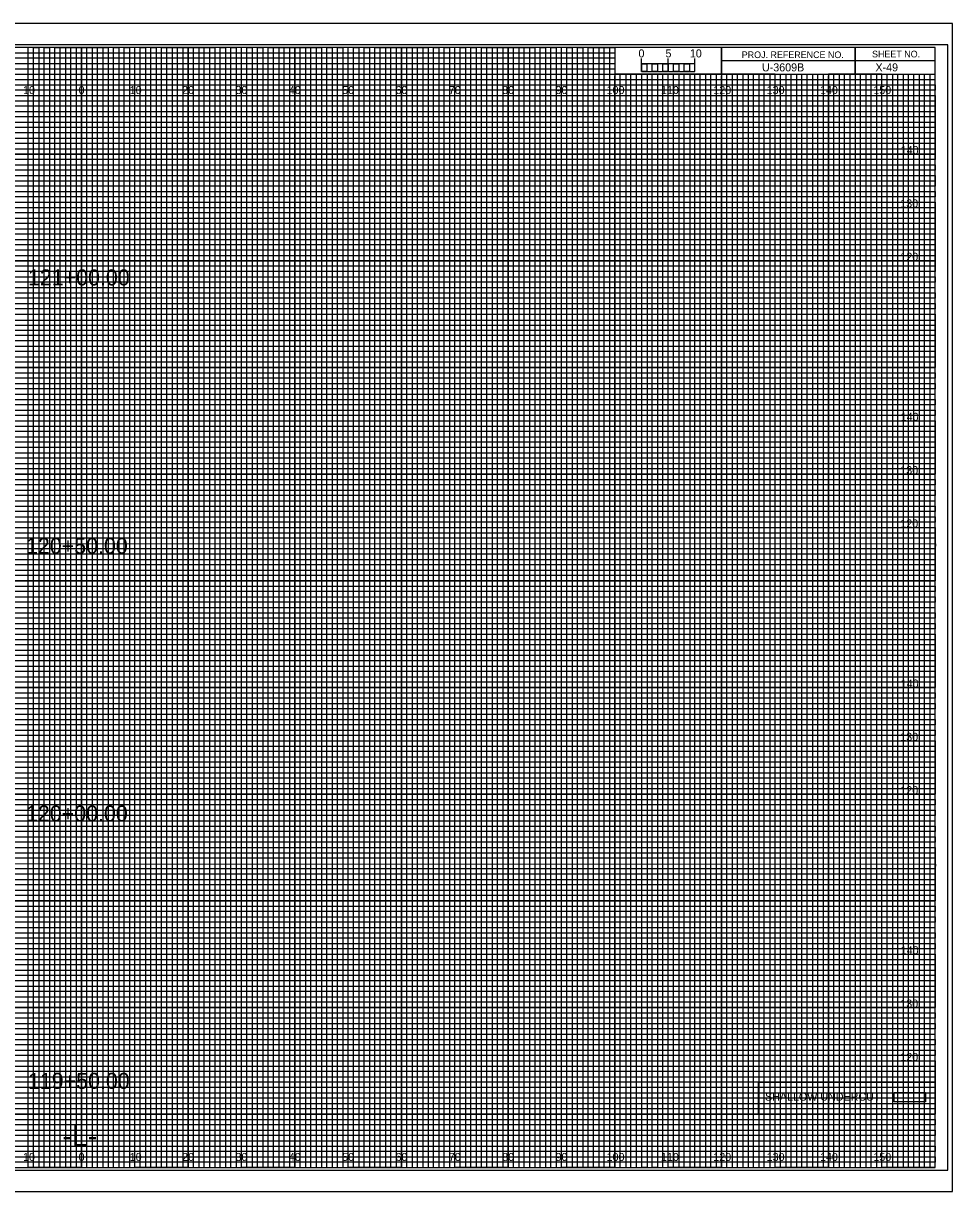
# Model space of a CAD drawing. Extents: x -13 to 329, y -17 to 10994.
# Drawn here: x 149.1 to 323.3, y 10335.5 to 10554.5 of the extents above; entities that cross this region are included whole.
import ezdxf

# ---------------------------------------------------------------- set-up
doc = ezdxf.new("R2010")
doc.units = 0
for name, color, linetype in [('Prop DSN Text', 7, 'Continuous'), ('Prop Grid Mask', 7, 'Continuous'), ('Prop Road Plan_ Recs - UC Shallow (pattern)', 7, 'Continuous'), ('Prop XS Alignment Label', 7, 'Continuous'), ('Prop XS Bar Scale Labels', 7, 'Continuous'), ('Prop XS Elevation Labels', 7, 'Continuous'), ('Prop XS Offset Labels', 7, 'Continuous'), ('Prop XS Project Number', 7, 'Continuous'), ('Prop XS Sheet Number', 7, 'Continuous'), ('Prop XS Station Labels', 7, 'Continuous'), ('Sheet Cross Section CELL', 7, 'Continuous'), ('Sheet Cross Section Grid Major CELL', 7, 'Continuous'), ('Sheet Cross Section Grid Middle CELL', 7, 'Continuous'), ('Sheet Cross Section Grid Minor 1 CELL', 7, 'Continuous'), ('Sheet Cross Section Grid Minor 2 CELL', 7, 'Continuous'), ('Sheet Cross Section Scale CELL', 7, 'Continuous'), ('Sheet Cutting Line CELL', 7, 'Continuous'), ('Sheet DOT Grid CELL', 7, 'Continuous'), ('Sheet Plot Border Inside CELL', 7, 'Continuous'), ('Sheet Plot Border Outside CELL', 7, 'Continuous')]:
    doc.layers.add(name, color=color, linetype=linetype)

msp = doc.modelspace()

# ---------------------------------------------------------------- linework, layer by layer
at = {"layer": 'Prop Grid Mask'}
msp.add_lwpolyline([(286.89, 10356.03), (320, 10356.03), (320, 10350), (286.89, 10350)], close=True, dxfattribs=at)
at = {"layer": 'Prop Road Plan_ Recs - UC Shallow (pattern)'}
msp.add_lwpolyline([(312.34, 10354.08), (318.23, 10354.08), (318.23, 10352.36), (312.34, 10352.36)], close=True, dxfattribs=at)
at = {"layer": 'Sheet Cross Section CELL'}
for p, q in [((305, 10550), (305, 10545)), ((305, 10545), (305, 10550)), ((280, 10547.5), (280, 10545)), ((320, 10547.49), (280, 10547.49)), ((280, 10545), (320, 10545))]:
    msp.add_line(p, q, dxfattribs=at)
for points in [[(320, 10550), (0, 10550), (0, 10340), (320, 10340)], [(280, 10550), (260, 10550), (260, 10545.03), (280, 10545.03)], [(320, 10550), (280, 10550), (280, 10545), (320, 10545)]]:
    msp.add_lwpolyline(points, close=True, dxfattribs=at)
at = {"layer": 'Sheet Cross Section Grid Major CELL'}
for p, q in [((150, 10550), (140, 10550)), ((150, 10340), (150, 10550)), ((170, 10550), (160, 10550)), ((160, 10550), (160, 10340)), ((170, 10340), (170, 10550)), ((190, 10550), (180, 10550)), ((180, 10550), (180, 10340)), ((190, 10340), (190, 10550)), ((210, 10550), (200, 10550)), ((200, 10550), (200, 10340)), ((210, 10340), (210, 10550)), ((230, 10550), (220, 10550)), ((220, 10550), (220, 10340)), ((230, 10340), (230, 10550)), ((250, 10550), (240, 10550)), ((240, 10550), (240, 10340)), ((250, 10340), (250, 10550)), ((260, 10550), (260, 10340)), ((270, 10340), (270, 10545)), ((290, 10545), (280, 10545)), ((280, 10545), (280, 10340)), ((290, 10340), (290, 10545)), ((310, 10545), (300, 10545)), ((300, 10545), (300, 10340)), ((310, 10340), (310, 10545)), ((160, 10340), (150, 10340)), ((180, 10340), (170, 10340)), ((200, 10340), (190, 10340)), ((220, 10340), (210, 10340)), ((240, 10340), (230, 10340)), ((260, 10340), (250, 10340)), ((280, 10340), (270, 10340)), ((300, 10340), (290, 10340)), ((320, 10340), (310, 10340)), ((320, 10340), (320, 10340))]:
    msp.add_line(p, q, dxfattribs=at)
for points in [[(0, 10540), (320, 10540), (320, 10530), (0, 10530)], [(0, 10520), (320, 10520), (320, 10510), (0, 10510)], [(0, 10500), (320, 10500), (320, 10490), (0, 10490)], [(0, 10480), (320, 10480), (320, 10470), (0, 10470)], [(0, 10460), (320, 10460), (320, 10450), (0, 10450)], [(0, 10440), (320, 10440), (320, 10430), (0, 10430)], [(0, 10420), (320, 10420), (320, 10410), (0, 10410)], [(0, 10400), (320, 10400), (320, 10390), (0, 10390)], [(0, 10380), (320, 10380), (320, 10370), (0, 10370)], [(0, 10360), (320, 10360), (320, 10350), (0, 10350)]]:
    msp.add_lwpolyline(points, dxfattribs=at)
at = {"layer": 'Sheet Cross Section Grid Middle CELL'}
for points in [[(145, 10340), (155, 10340), (155, 10550), (165, 10550), (165, 10340), (175, 10340), (175, 10550), (185, 10550), (185, 10340), (195, 10340), (195, 10550), (205, 10550), (205, 10340), (215, 10340), (215, 10550), (225, 10550), (225, 10340), (235, 10340), (235, 10550), (245, 10550), (245, 10340), (255, 10340), (255, 10550), (259.93, 10550), (260, 10550), (260, 10545), (264.99, 10545), (264.99, 10340), (275, 10340), (275, 10545), (285, 10545), (285, 10340), (295, 10340), (295, 10545), (305, 10545), (305, 10340), (315, 10340), (315, 10545)], [(0, 10545), (275, 10545)], [(0, 10525), (320, 10525), (320, 10535), (0, 10535)], [(0, 10505), (320, 10505), (320, 10515), (0, 10515)], [(0, 10485), (320, 10485), (320, 10495), (0, 10495)], [(0, 10465), (320, 10465), (320, 10475), (0, 10475)], [(0, 10445), (320, 10445), (320, 10455), (0, 10455)], [(0, 10425), (320, 10425), (320, 10435), (0, 10435)], [(0, 10405), (320, 10405), (320, 10415), (0, 10415)], [(0, 10385), (320, 10385), (320, 10395), (0, 10395)], [(0, 10365), (320, 10365), (320, 10375), (0, 10375)], [(0, 10345), (320, 10345), (320, 10355), (0, 10355)]]:
    msp.add_lwpolyline(points, dxfattribs=at)
at = {"layer": 'Sheet Cross Section Grid Minor 1 CELL'}
for p, q in [((0, 10549), (260, 10549)), ((260, 10547.98), (0, 10547.98)), ((260, 10549), (260, 10547.98)), ((0, 10547), (260, 10547)), ((260, 10545.89), (0, 10545.89)), ((260, 10547), (260, 10545.89)), ((0, 10544), (320, 10544))]:
    msp.add_line(p, q, dxfattribs=at)
for points in [[(0, 10543), (270, 10543), (320, 10543), (320, 10542), (0, 10542)], [(0, 10541), (320, 10541), (320, 10539), (0, 10539)], [(0, 10538), (320, 10538), (320, 10537), (0, 10536.98)], [(0, 10536), (320, 10536), (320, 10534), (0, 10534)], [(0, 10533), (320, 10533), (320, 10532), (0, 10532)], [(0, 10531), (320, 10531), (320, 10529), (0, 10529)], [(0, 10528), (320, 10528), (320, 10527), (0, 10527)], [(0, 10526), (320, 10526), (320, 10524), (0, 10524)], [(0, 10523), (320, 10523), (320, 10522), (0, 10522)], [(0, 10521), (320, 10521), (320, 10519), (0, 10519)], [(0, 10518), (320, 10518), (320, 10517), (0, 10517)], [(0, 10516), (320, 10516), (320, 10513.95), (320, 10513), (320, 10512), (0, 10512)], [(0, 10514), (320, 10514), (320, 10513), (0, 10513)], [(0, 10511), (320, 10511), (320, 10509), (0, 10509.03)], [(0, 10509.03), (320, 10509), (320, 10508), (0, 10508)], [(0, 10507), (320, 10507), (320, 10506), (0, 10506)], [(0, 10504), (320, 10504), (320, 10503), (0, 10503)], [(0, 10502), (320, 10502), (320, 10501), (0, 10501)], [(-0.07, 10498.89), (320, 10498.89), (320, 10497.88), (-0.07, 10497.88)], [(0, 10497), (320, 10497), (320, 10496), (0, 10496)], [(0, 10494), (320, 10494), (320, 10493), (0, 10493)], [(0, 10492), (320, 10492), (320, 10491), (0, 10491)], [(0, 10489), (320, 10489), (320, 10488), (0, 10488)], [(0, 10487), (320, 10487), (320, 10486), (0, 10486)], [(0, 10484), (320, 10484), (320, 10483), (0, 10483)], [(0, 10482), (320, 10482), (320, 10481), (0, 10481)], [(0, 10479), (320, 10479), (319.99, 10477.98), (0, 10478)], [(0, 10477), (320, 10477), (320, 10476), (0, 10476)], [(0, 10474), (320, 10474), (320, 10473), (0, 10473)], [(0, 10472), (320, 10472), (320, 10471), (0, 10471)], [(0, 10469), (320, 10469), (320, 10468), (0, 10468)], [(0, 10467), (320, 10467), (320, 10466), (0, 10466)], [(0, 10464), (320, 10464), (320, 10463), (0, 10463)], [(0, 10462), (320, 10462), (320, 10461), (0, 10461)], [(0, 10459), (320, 10459), (320, 10458), (0, 10458)], [(0, 10456.99), (320.07, 10456.91), (320, 10456), (0, 10456)], [(0, 10454), (320, 10454), (320, 10453), (0, 10453)], [(0, 10452), (320, 10452), (320, 10451), (0, 10451)], [(0, 10449), (320, 10449), (320, 10448), (0, 10448)], [(0, 10447), (320, 10447), (320, 10446), (0, 10446)], [(0, 10444), (320, 10444), (320, 10443), (0, 10443)], [(0, 10442), (320, 10442), (320, 10441), (0, 10441)], [(0, 10439), (320, 10439), (320, 10438), (0, 10438)], [(0, 10437), (320, 10437), (320, 10436), (0, 10436)], [(0, 10434), (320, 10434), (320, 10433), (0, 10433)], [(0, 10432), (320, 10432), (320, 10431), (0, 10431)], [(0, 10429), (320, 10429), (320, 10428), (0, 10428)], [(0, 10427), (320, 10427), (320, 10426), (0, 10426)], [(0, 10424), (320, 10424), (320, 10423), (0, 10423)], [(0, 10422), (320, 10422), (320, 10421), (0, 10421)], [(0, 10419), (320, 10419), (319.99, 10417.98), (0, 10418)], [(0, 10417), (320, 10417), (320, 10416), (0, 10416)], [(0, 10414), (320, 10414), (320, 10413), (0, 10413)], [(0, 10412), (320, 10412), (320, 10411), (0, 10411)], [(0, 10409), (320, 10409), (320, 10408), (0, 10408)], [(0, 10407), (320, 10407), (320, 10406), (0, 10406)], [(0, 10404), (320, 10404), (320, 10403), (0, 10403)], [(0, 10402), (320, 10402), (320, 10401), (0, 10401)], [(0, 10399), (320, 10399), (320, 10398), (0, 10398)], [(0, 10396.99), (320.07, 10396.91), (320, 10396), (0, 10396)], [(0, 10394), (320, 10394), (320, 10393), (0, 10393)], [(0, 10392), (320, 10392), (320, 10391), (0, 10391)], [(0, 10389), (320, 10389), (320, 10388), (0, 10388)], [(0, 10387), (320, 10387), (320, 10386), (0, 10386)], [(0, 10384), (320, 10384), (320, 10383), (0, 10383)], [(0, 10382), (320, 10382), (320, 10381), (0, 10381)], [(0, 10379), (320, 10379), (320, 10378), (0, 10378)], [(0, 10377), (320, 10377), (320, 10376), (0, 10376)], [(0, 10374), (320, 10374), (320, 10373), (0, 10373)], [(0, 10372), (320, 10372), (320, 10371), (0, 10371)], [(0, 10369), (320, 10369), (320, 10368), (0, 10368)], [(0, 10367), (320, 10367), (320, 10366), (0, 10366)], [(0, 10364), (320, 10364), (320, 10363), (0, 10363)], [(0, 10362), (320, 10362), (320, 10361), (0, 10361)], [(0, 10359), (320, 10359), (320, 10358), (0, 10358)], [(0, 10357), (320, 10357), (320, 10356), (0, 10356)], [(0, 10354), (320, 10354), (320, 10353), (0, 10353)], [(0, 10352), (320, 10352), (320, 10351), (0, 10351)], [(0, 10349), (320, 10349), (320, 10348), (0, 10348)], [(0, 10347), (320, 10347), (320, 10346), (0, 10346)], [(0, 10344), (320, 10344), (320, 10343), (0, 10343)], [(0, 10342), (320, 10342), (320, 10341), (0, 10341)]]:
    msp.add_lwpolyline(points, dxfattribs=at)
at = {"layer": 'Sheet Cross Section Grid Minor 2 CELL'}
for p, q in [((267, 10545), (266.01, 10545)), ((266.01, 10545), (266.01, 10340)), ((267, 10340), (267, 10545)), ((269, 10545), (268, 10545)), ((268, 10545), (268, 10340)), ((269, 10340), (269, 10545)), ((266.01, 10340), (265, 10340)), ((268, 10340), (267, 10340))]:
    msp.add_line(p, q, dxfattribs=at)
for points in [[(150, 10340), (151, 10340), (151, 10550), (152, 10550), (152, 10340)], [(152, 10340), (153, 10340), (153, 10550), (154, 10550), (154, 10340)], [(155, 10340), (156, 10340), (156, 10550), (157, 10550), (157, 10340)], [(157, 10340), (158, 10340), (158, 10550), (159, 10550), (159, 10340)], [(160, 10340), (161, 10340), (161, 10550), (162, 10550), (162, 10340)], [(162, 10340), (163, 10340), (163, 10550), (164, 10550), (164, 10340)], [(165, 10340), (166, 10340), (166, 10550), (167, 10550), (167, 10340)], [(167, 10340), (168, 10340), (168, 10550), (169, 10550), (169, 10340)], [(170, 10340), (171, 10340), (171, 10550), (172, 10550), (172, 10340)], [(172, 10340), (173, 10340), (173, 10550), (174, 10550), (174, 10340)], [(175, 10340), (176, 10340), (176, 10550), (177, 10550), (177, 10340)], [(177, 10340), (178, 10340), (178, 10550), (179, 10550), (179, 10340)], [(180, 10340), (181, 10340), (181, 10550), (182, 10550), (182, 10340)], [(182, 10340), (183, 10340), (183, 10550), (184, 10550), (184, 10340)], [(185, 10340), (186, 10340), (186, 10550), (187, 10550), (187, 10340)], [(187, 10340), (188, 10340), (188, 10550), (189, 10550), (189, 10340)], [(190, 10340), (191, 10340), (191, 10550), (192, 10550), (192, 10340)], [(192, 10340), (193, 10340), (193, 10550), (194, 10550), (194, 10340)], [(195, 10340), (196, 10340), (196, 10550), (197, 10550), (197, 10340)], [(197, 10340), (198, 10340), (198, 10550), (199, 10550), (199, 10340)], [(200, 10340), (201, 10340), (201, 10550), (202, 10550), (202, 10340)], [(202, 10340), (203, 10340), (203, 10550), (204, 10550), (204, 10340)], [(205, 10340), (206, 10340), (206, 10550), (207, 10550), (207, 10340)], [(207, 10340), (208, 10340), (208, 10550), (209, 10550), (209, 10340)], [(210, 10340), (211, 10340), (211, 10550), (212, 10550), (212, 10340)], [(212, 10340), (213, 10340), (213, 10550), (214, 10550), (214, 10340)], [(215, 10340), (216, 10340), (216, 10550), (217, 10550), (217, 10340)], [(217, 10340), (218, 10340), (218, 10550), (219, 10550), (219, 10340)], [(220, 10340), (221, 10340), (221, 10550), (222, 10550), (222, 10340)], [(222, 10340), (223, 10340), (223, 10550), (224, 10550), (224, 10340)], [(225, 10340), (226, 10340), (226, 10550), (227, 10550), (227, 10340)], [(227, 10340), (228, 10340), (228, 10550), (229, 10550), (229, 10340)], [(230, 10340), (231, 10340), (231, 10550), (232, 10550), (232, 10340)], [(232, 10340), (233, 10340), (233, 10550), (234, 10550), (234, 10340)], [(235, 10340), (236, 10340), (236, 10550), (237, 10550), (237, 10340)], [(237, 10340), (238, 10340), (238, 10550), (239, 10550), (239, 10340)], [(240, 10340), (241, 10340), (241, 10550), (242, 10550), (242, 10340)], [(242, 10340), (243, 10340), (243, 10550), (244, 10550), (244, 10340)], [(245, 10340), (246, 10340), (246, 10550), (247, 10550), (247, 10340)], [(247, 10340), (248, 10340), (248, 10550), (249, 10550), (249, 10340)], [(250, 10340), (251, 10340), (251, 10550), (252, 10550), (252, 10340)], [(252, 10340), (253, 10340), (253, 10550), (254, 10550), (254, 10340)], [(255, 10340), (256, 10340), (256, 10550), (257, 10550), (257, 10340)], [(257, 10340), (258, 10340), (258, 10550), (259, 10550), (259, 10340)], [(260, 10340), (261, 10340), (261, 10545), (262.02, 10545), (262.02, 10340)], [(262, 10340), (263, 10340), (263, 10545), (263.99, 10545), (263.99, 10340)], [(270, 10340), (270.98, 10340), (270.98, 10545), (272, 10545), (272, 10340)], [(272, 10340), (273, 10340), (273, 10545), (274.05, 10545), (274.05, 10340)], [(275, 10340), (276, 10340), (276, 10545), (277, 10545), (277, 10340)], [(277, 10340), (278, 10340), (278, 10545), (279, 10545), (279, 10340)], [(280, 10340), (281, 10340), (281, 10545), (282, 10545), (282, 10340)], [(282, 10340), (283, 10340), (283, 10545), (284, 10545), (284, 10340)], [(285, 10340), (286, 10340), (286, 10545), (287, 10545), (287, 10340)], [(287, 10340), (288, 10340), (288, 10545), (289, 10545), (289, 10340)], [(290, 10340), (291, 10340), (291, 10545), (292, 10545), (292, 10340)], [(292, 10340), (293, 10340), (293, 10545), (294, 10545), (294, 10340)], [(295, 10340), (296, 10340), (296, 10545), (297, 10545), (297, 10340)], [(297, 10340), (298, 10340), (298, 10545), (299, 10545), (299, 10340)], [(300, 10340), (301, 10340), (301, 10545), (302, 10545), (302, 10340)], [(302, 10340), (303, 10340), (303, 10545), (304, 10545), (304, 10340)], [(305, 10340), (306, 10340), (306, 10545), (307, 10545), (307, 10340)], [(307, 10340), (308, 10340), (308, 10545), (309, 10545), (309, 10340)], [(310, 10340), (311, 10340), (311, 10545), (312, 10545), (312, 10340)], [(312, 10340), (313, 10340), (313, 10545), (314, 10545), (314, 10340)], [(315, 10340), (316, 10340), (316, 10545), (317, 10545), (317, 10340)], [(317, 10340), (318, 10340), (318, 10545), (319, 10545), (319, 10340)]]:
    msp.add_lwpolyline(points, dxfattribs=at)
at = {"layer": 'Sheet Cross Section Scale CELL'}
for p, q in [((265, 10545.49), (265, 10547.9)), ((265, 10546.9), (265, 10547.9)), ((270, 10545.49), (270, 10547.9)), ((275, 10545.49), (275, 10547.9)), ((275, 10546.9), (275, 10547.9))]:
    msp.add_line(p, q, dxfattribs=at)
for points in [[(275, 10546.9), (265, 10546.9), (265, 10545.49), (275, 10545.49)], [(265, 10546.9), (266, 10546.9), (266, 10545.49), (265, 10545.49)], [(267, 10546.9), (268, 10546.9), (268, 10545.49), (267, 10545.49)], [(269, 10546.9), (270, 10546.9), (270, 10545.49), (269, 10545.49)], [(271, 10546.9), (272, 10546.9), (272, 10545.49), (271, 10545.49)], [(273, 10546.9), (274, 10546.9), (274, 10545.49), (273, 10545.49)]]:
    msp.add_lwpolyline(points, close=True, dxfattribs=at)
at = {"layer": 'Sheet Cutting Line CELL'}
for p, q in [((323.3, 10554.5), (-13.4, 10554.5)), ((-13.4, 10335.5), (323.3, 10335.5))]:
    msp.add_line(p, q, dxfattribs=at)
at = {"layer": 'Sheet DOT Grid CELL'}
for p, q in [((150, 10340), (150, 10550)), ((160, 10340), (160, 10550)), ((170, 10340), (170, 10550)), ((180, 10340), (180, 10550)), ((190, 10340), (190, 10550)), ((200, 10340), (200, 10550)), ((210, 10340), (210, 10550)), ((220, 10340), (220, 10550)), ((230, 10340), (230, 10550)), ((240, 10340), (240, 10550)), ((250, 10340), (250, 10550)), ((260, 10340), (260, 10544.69)), ((270, 10340), (270, 10544.69)), ((280, 10340), (280, 10544.69)), ((290, 10340), (290, 10544.69)), ((300, 10340), (300, 10544.69)), ((310, 10340), (310, 10544.69)), ((0, 10540), (320, 10540)), ((0, 10530), (320, 10530)), ((0, 10520), (320, 10520)), ((0, 10510), (320, 10510)), ((0, 10500), (320, 10500)), ((0, 10490), (320, 10490)), ((0, 10480), (320, 10480)), ((0, 10470), (320, 10470)), ((0, 10460), (320, 10460)), ((0, 10450), (320, 10450)), ((0, 10440), (320, 10440)), ((0, 10430), (320, 10430)), ((0, 10420), (320, 10420)), ((0, 10410), (320, 10410)), ((0, 10400), (320, 10400)), ((0, 10390), (320, 10390)), ((0, 10380), (320, 10380)), ((0, 10370), (320, 10370)), ((0, 10360), (320, 10360)), ((0, 10350), (320, 10350))]:
    msp.add_line(p, q, dxfattribs=at)
at = {"layer": 'Sheet Plot Border Inside CELL'}
msp.add_lwpolyline([(-10.8, 10339.5), (322.4, 10339.5), (322.4, 10550.5), (-10.8, 10550.5)], close=True, dxfattribs=at)
at = {"layer": 'Sheet Plot Border Outside CELL'}
msp.add_lwpolyline([(-13.4, 10335.5), (323.3, 10335.5), (323.3, 10554.5), (-13.4, 10554.5)], close=True, dxfattribs=at)

# ---------------------------------------------------------------- texts
at = {"layer": 'Prop DSN Text'}
msp.add_text('SHALLOW UNDERCUT', height=1.5, dxfattribs=at).set_placement((288.13, 10352.55))
at = {"layer": 'Prop XS Alignment Label'}
msp.add_text('-L-', height=4, dxfattribs=at).set_placement((156.42, 10344))
at = {"layer": 'Prop XS Bar Scale Labels'}
for s, p in [('5', (269.47, 10548.12)), ('10', (274.04, 10548.12))]:
    msp.add_text(s, height=1.5, dxfattribs=at).set_placement(p)
at = {"layer": 'Prop XS Elevation Labels'}
for s, p in [('140', (313.57, 10530)), ('130', (313.49, 10520)), ('120', (313.5, 10510)), ('140', (313.57, 10480)), ('130', (313.49, 10470)), ('120', (313.5, 10460)), ('140', (313.57, 10430)), ('130', (313.49, 10420)), ('120', (313.5, 10410)), ('140', (313.57, 10380)), ('130', (313.49, 10370)), ('120', (313.5, 10360))]:
    msp.add_text(s, height=1.5, dxfattribs=at).set_placement(p)
at = {"layer": 'Prop XS Offset Labels'}
for s, p in [('10', (149.04, 10541.25)), ('0', (159.45, 10541.25)), ('0', (159.45, 10541.25)), ('10', (169.04, 10541.25)), ('20', (178.86, 10541.25)), ('30', (188.86, 10541.25)), ('40', (198.86, 10541.25)), ('50', (208.86, 10541.25)), ('60', (218.86, 10541.25)), ('70', (228.86, 10541.25)), ('80', (238.86, 10541.25)), ('90', (248.86, 10541.25)), ('100', (258.44, 10541.25)), ('110', (268.62, 10541.25)), ('120', (278.44, 10541.25)), ('130', (288.44, 10541.25)), ('140', (298.44, 10541.25)), ('150', (308.44, 10541.25)), ('10', (149.04, 10341.25)), ('0', (159.45, 10341.25)), ('0', (159.45, 10341.25)), ('10', (169.04, 10341.25)), ('20', (178.86, 10341.25)), ('30', (188.86, 10341.25)), ('40', (198.86, 10341.25)), ('50', (208.86, 10341.25)), ('60', (218.86, 10341.25)), ('70', (228.86, 10341.25)), ('80', (238.86, 10341.25)), ('90', (248.86, 10341.25)), ('100', (258.44, 10341.25)), ('110', (268.62, 10341.25)), ('120', (278.44, 10341.25)), ('130', (288.44, 10341.25)), ('140', (298.44, 10341.25)), ('150', (308.44, 10341.25))]:
    msp.add_text(s, height=1.5, dxfattribs=at).set_placement(p)
at = {"layer": 'Prop XS Project Number'}
msp.add_text('U-3609B', height=1.5, dxfattribs=at).set_placement((287.56, 10545.5))
at = {"layer": 'Prop XS Sheet Number'}
msp.add_text('X-49', height=1.5, dxfattribs=at).set_placement((308.83, 10545.5))
at = {"layer": 'Prop XS Station Labels'}
for s, p in [('121+00.00', (149.95, 10505.38)), ('120+50.00', (149.59, 10455.07)), ('120+00.00', (149.59, 10404.89)), ('119+50.00', (149.95, 10354.77))]:
    msp.add_text(s, height=3, dxfattribs=at).set_placement(p)
at = {"layer": 'Sheet Cross Section CELL'}
for s, p in [('PROJ. REFERENCE NO.', (283.77, 10547.99)), ('SHEET NO.', (308.19, 10548.12))]:
    msp.add_text(s, height=1.25, dxfattribs=at).set_placement(p)
at = {"layer": 'Sheet Cross Section Scale CELL'}
msp.add_text('0', height=1.5, dxfattribs=at).set_placement((264.41, 10548.12))

doc.saveas('drawing.dxf')
